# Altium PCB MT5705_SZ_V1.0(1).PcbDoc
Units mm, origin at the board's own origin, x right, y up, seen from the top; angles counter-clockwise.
Board outline 17 x 17 mm, 2 copper layers (Top Layer, Bottom Layer), stack 0.325 mm thick; 41 components, 24 nets, 105 pads, 55 vias.
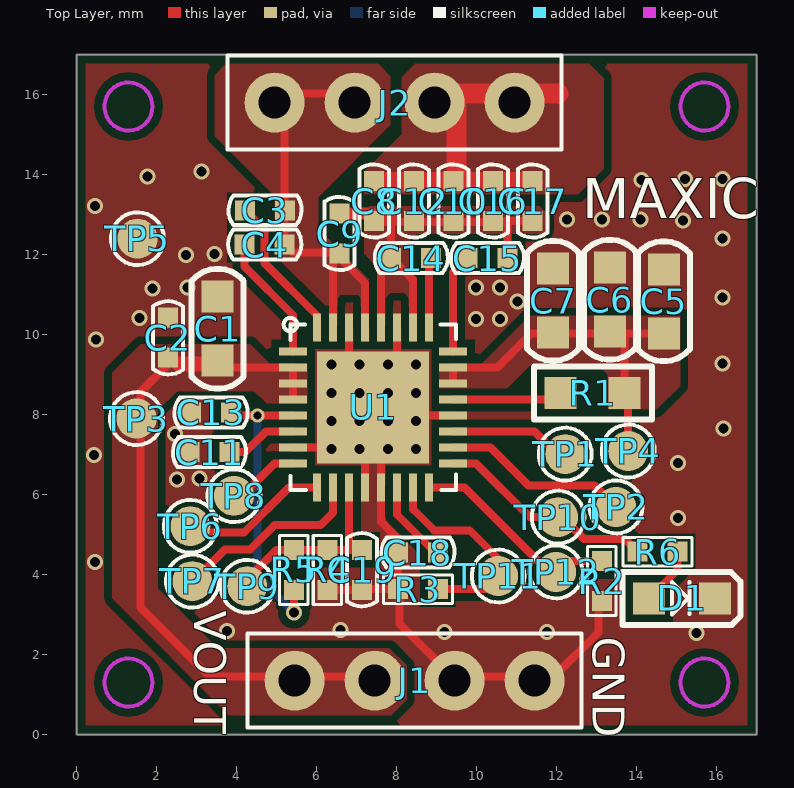
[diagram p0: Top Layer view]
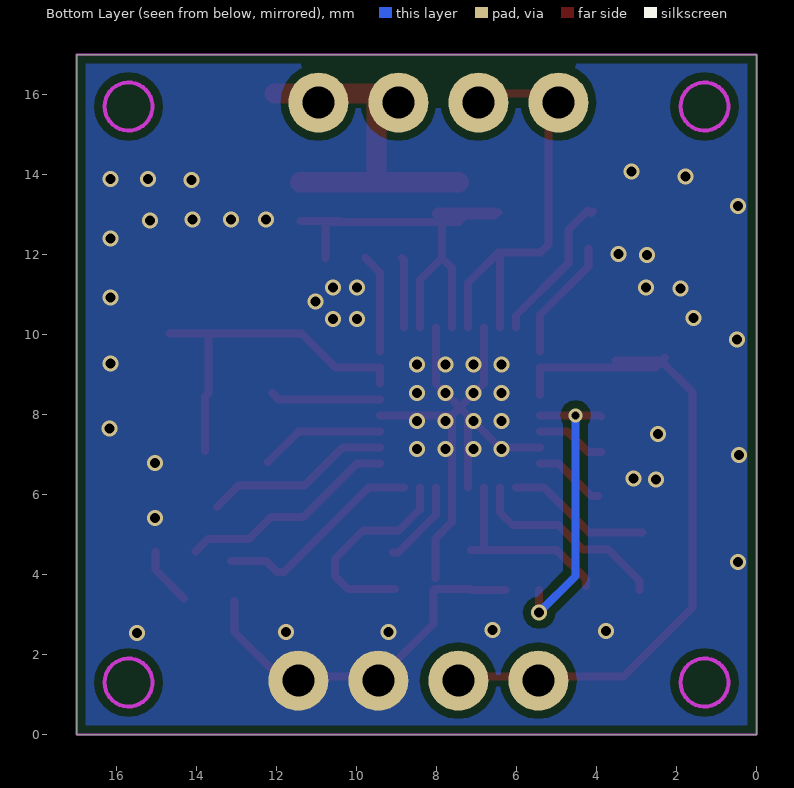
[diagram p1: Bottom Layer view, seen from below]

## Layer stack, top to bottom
Top Solder: solder mask 0.0102, Solder Resist, Dk 3.5
Top Layer: signal copper 0.0356
Dielectric 1: core 0.254, FR-4, Dk 4.2
Bottom Layer: signal copper 0.0356
Bottom Solder: solder mask 0.0102, Solder Resist, Dk 3.5

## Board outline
0,0 17,0 17,17 0,17

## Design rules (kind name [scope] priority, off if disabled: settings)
Clearance Clearance_0.1 [All] p1: gap=0.1
Clearance Clearance_0.2 [All] p2 off: gap=0.2
Clearance Clearance_0.3 [All] p3 off: gap=0.3
ComponentClearance [All] p1 off: gap=0 collisioncheckmode=3 verticalgap=0 showdistances=FALSE
DiffPairsRouting [All] p1: maxlimit=2 minlimit=0.2 mostfreqgap=0.3 toplayer_minwidth=0.2 toplayer_maxwidth=2 toplayer_prefwidth=0.3 bottomlayer_minwidth=0.2 bottomlayer_maxwidth=2 bottomlayer_prefwidth=0.3 maxuncoupledlength=12.7
HoleSize [All] p1: absolutevalues=TRUE maxlimit=5 minlimit=0.025 maxpercent=80.000 minpercent=20.000
HoleToHoleClearance [All] p1: gap=0.2 allowstackedmicrovias=TRUE
MinimumSolderMaskSliver [All] p1: minsoldermaskwidth=0
PlaneConnect [All] p1: planeconnectstyle=Direct reliefexpansion=0.508 reliefentries=4 reliefconductorwidth=0.254 reliefairgap=0.254
PolygonConnect [All] p1: connectstyle=Direct reliefconductorwidth=0.254 reliefentries=4 polygonreliefangle="90 Angle" airgapwidth=0.254
RoutingCorners [All] p1 off: cornerstyle=45-Degree minsetback=2.54 maxsetback=2.54
RoutingVias [All] p1: holewidth=0.4 width=0.7 viastyle="Through Hole" minholewidth=0.25 minwidth=0.4 maxholewidth=1.6 maxwidth=2
SilkToSilkClearance [All] p1: silktosilkclearance=0
SilkToSolderMaskClearance [IsPad] p1: minsilkscreentomaskgap=0 clearancetoexposedcopper=TRUE
SolderMaskExpansion [All] p1: expansion=0.102
Width [All] p1: maxlimit=2 minlimit=0.2 preferedwidth=0.3 minimp=50.000000 maximp=50.000000 favimp=50.000000
20 further rules are at their usual default settings.

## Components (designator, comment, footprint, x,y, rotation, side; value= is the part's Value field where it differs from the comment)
C1 "10uF" 0603C 3.531,10.145 r90 top
C2 "100nF" 0402C 2.286,9.921 r270 top
C3 "15nF" 0402C 4.709,13.106 r0 top
C4 "32nF" 0402C 4.702,12.25 r0 top
C5 "10uF" 0603C 14.681,10.831 r90 top
C6 "10uF" 0603C 13.335,10.871 r90 top
C7 "10uF" 0603C 11.913,10.846 r90 top
C8 "100nF" 0402C 7.442,13.335 r90 top
C9 "3.3nF" 0402C 6.579,12.522 r90 top
C10 "100nF" 0402C 9.423,13.335 r90 top
C11 "1uF" 0402C 3.327,7.061 r180 top
C12 "100nF" 0402C 8.433,13.335 r90 top
C13 "1uF" 0402C 3.368,8.052 r180 top
C14 "15nF" 0402C 8.367,11.913 r0 top
C15 "32nF" 0402C 10.277,11.913 r180 top
C16 "100nF" 0402C 10.414,13.335 r90 top
C17 "NC" 0402C 11.405,13.335 r90 top
C18 "100nF" 0402C 8.534,4.547 r0 top
C19 "100nF" 0402C 7.137,4.115 r90 top
D1 "GREEN" D0603 15.138,3.404 r0 top
J1 "4 HEADER" SIP4-2.00mm 11.455,1.346 r180 top
J2 "COIL" SIP4-2.00mm 4.953,15.799 r0 top
R1 "NC" 0603R 12.903,8.534 r0 top
R2 "100K" 0402R 13.132,3.835 r90 top
R3 "100K" 0402R 8.534,3.632 r0 top
R4 "100K" 0402R 6.274,4.115 r90 top
R5 "NC" 0402R 5.436,4.115 r270 top
R6 "2K" 0402R 14.529,4.572 r180 top
TP1 "" TEST-PAD-S 12.217,7.01 r90 top
TP2 "" TEST-PAD-S 13.487,5.69 r90 top
TP3 "" TEST-PAD-S 1.499,7.899 r90 top
TP4 "" TEST-PAD-S 13.792,7.087 r90 top
TP5 "" TEST-PAD-S 1.524,12.395 r90 top
TP6 "" TEST-PAD-S 2.845,5.207 r90 top
TP7 "" TEST-PAD-S 2.896,3.835 r90 top
TP8 "" TEST-PAD-S 3.937,5.969 r90 top
TP9 "" TEST-PAD-S 4.267,3.708 r90 top
TP10 "" TEST-PAD-S 12.04,5.436 r90 top
TP11 "" TEST-PAD-S 10.541,3.962 r90 top
TP12 "" TEST-PAD-S 11.989,4.064 r90 top
U1 "MT5705" QFN32-EPAD 7.417,8.179 r0 top

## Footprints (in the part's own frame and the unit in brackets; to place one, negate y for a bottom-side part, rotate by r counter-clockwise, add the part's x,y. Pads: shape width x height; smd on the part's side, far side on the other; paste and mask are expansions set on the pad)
0402C [mm]
  rect 0.5x0.5 smd: 1(-0.5,0) 2(0.5,0)
  silkscreen extent -0.91,-0.37 0.92,0.37, body extent -0.5,-0.25 0.5,0.25, height 0.5
0402R [mm]
  rect 0.5x0.5 smd: 1(-0.5,0) 2(0.5,0)
  silkscreen extent -0.86,-0.36 0.86,0.36, body extent -0.5,-0.25 0.5,0.25, height 0.35
0603C [mm]
  rect 0.8x0.8 smd: 1(-0.8,0) 2(0.8,0)
  silkscreen extent -1.5,-0.65 1.5,0.65, body extent -0.8,-0.41 0.8,0.4, height 0.8
0603R [mm]
  rect 0.8x0.8 smd: 1(-0.8,0) 2(0.8,0)
  silkscreen extent -1.46,-0.66 1.49,0.66, body extent -0.8,-0.4 0.8,0.41, height 0.45
D0603 [mm]
  rect 0.8x0.8 smd mask+0.01: A(-0.826,0) K(0.826,0)
  silkscreen extent -1.49,-0.66 1.46,0.66, body extent -0.8,-0.4 0.8,0.4, height 0.6
QFN32-EPAD [mm]
  rect 0.7x0.2 smd mask+0.01: 1(-2,1.4) 2(-2,1) 3(-2,0.6) 4(-2,0.2) 5(-2,-0.2) 6(-2,-0.6) 7(-2,-1) 8(-2,-1.4) 17(2,-1.4) 18(2,-1) 19(2,-0.6) 20(2,-0.2) 21(2,0.2) 22(2,0.6) 23(2,1) 24(2,1.4)
  rect 0.2x0.7 smd mask+0.01: 9(-1.4,-2) 10(-1,-2) 11(-0.6,-2) 12(-0.2,-2) 13(0.2,-2) 14(0.6,-2) 15(1,-2) 16(1.4,-2) 25(1.4,2) 26(1,2) 27(0.6,2) 28(0.2,2) 29(-0.2,2) 30(-0.6,2) 31(-1,2) 32(-1.4,2)
  rect 2.8x2.8 smd mask+0.01: 33(0,0)
  silkscreen extent -2.24,-2.07 2.07,2.24
SIP4-2.00mm [mm]
  round 1.5 hole 0.8: 1(0,0) 2(2,0) 3(4,0) 4(6,0)
  silkscreen extent -1.17,-1.17 7.17,1.17, body extent -1,-1 7,1, height 6
TEST-PAD-S [mm]
  round 1 smd: 1(0,0)
  silkscreen extent -0.66,-0.66 0.66,0.66

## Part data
C1 C2 C3 C4 C5 C6 C7 C8 C9 C10 C11 C12 C13 C14 C15 C16 C17 C18 C19: library part CAP, "Capacitor"
D1: library part LED-GREEN
J1: "4 Pin Header"
J2: library part "4 HEADER", "4 Pin Header"
R1 R2 R3 R4 R5 R6: library part RES
TP1 TP2 TP3 TP4 TP5 TP6 TP7 TP8 TP9 TP10 TP11 TP12: library part TEST-PAD
U1: library part MT5705_QFN32

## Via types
v1: diameter 0.4, hole 0.25, Top Layer to Bottom Layer, 54 vias
v2: diameter 0.35, hole 0.2, Top Layer to Bottom Layer, 1 vias

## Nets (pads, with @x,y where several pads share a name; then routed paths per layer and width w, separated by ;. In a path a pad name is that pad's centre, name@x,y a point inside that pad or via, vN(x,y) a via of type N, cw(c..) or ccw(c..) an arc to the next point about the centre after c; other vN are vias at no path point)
ACN: C8.1 C9.2 C10.1 C12.1 C14.1 C15.1 C16.1 C17.1 U1.26 U1.28 | length 11.8
  Top Layer w0.2: C9.2@6.452,13.048 C9.2@6.579,13.048 ; C8.1@7.23,13.022 7.442,12.81 7.874,12.81 ; U1.28 7.617,11.662 C14.1 ; U1.26 8.417,11.363 C14.1 ; C16.1 C17.1 ; C15.1 10.777,12.766 10.82,12.81 7.874,12.81 ; C14.1 7.867,12.803 7.874,12.81
  Top Layer w0.3: C9.2 7.23,13.022 7.968,13.022
ACP: C3.2 C4.2 C9.1 J2.1 J2.2 U1.29 U1.31 | length 11.9
  Top Layer w0.2: J2.1@4.42,16.027 J2.1@5.461,16.027 ; U1.31 C9.1@6.417,12.048 ; J2.2@6.96,16.027 J2.1@5.461,16.027 ; U1.29 7.217,11.282 6.452,12.048 C9.1@6.417,12.048 ; J2.1@5.461,16.027 5.54,15.949 5.202,15.612 C4.2 5.405,12.048 C9.1@6.417,12.048
GND: C1.2 C2.1 C5.2 C6.2 C7.2 C11.2 C13.2 C18.1 C19.1 D1.K J1.1 J1.2 R2.1 R3.1 R4.1 TP5.1 U1.7 U1.12 U1.13 U1.20 U1.27 U1.30 U1.33 | length 24.4
  Top Layer w0.2: U1.7 6.417,7.179 U1.33@7.217,7.979 ; U1.30 6.817,8.779 U1.33 ; C19.1@7.163,3.615 7.18,3.632 R3.1 ; U1.12 U1.33@7.217,7.979 ; U1.27 8.017,8.779 U1.33 ; 8.026,3.91 8.026,4.902 7.617,5.312 U1.13 U1.33@7.617,7.979 ; R3.1@8.077,3.615 8.077,2.769 9.398,1.448 11.938,1.448 13.056,2.565 R2.1@13.056,3.335 ; U1.20 U1.33@7.617,7.979 ; U1.33@7.217,7.979 U1.33 ; U1.33 U1.33@7.617,7.979
  Top Layer w0.203: R4.1 C19.1 C19.1@7.163,3.615
  other v1: 15.494,2.54 9.195,2.565 11.76,2.565 3.759,2.591 6.604,2.616 0.457,4.318 15.037,5.41 2.515,6.375 3.073,6.401 15.037,6.782 0.432,6.985 6.375,7.137 7.078,7.137 7.781,7.137 8.484,7.137 2.464,7.518 16.18,7.645 6.375,7.84 7.078,7.84 7.781,7.84 8.484,7.84 6.375,8.543 7.078,8.543 7.781,8.543 8.484,8.543 6.375,9.246 7.078,9.246 7.781,9.246 8.484,9.246 16.154,9.271 0.483,9.881 9.982,10.389 10.592,10.389 1.575,10.414 11.024,10.82 16.154,10.922 1.905,11.151 2.769,11.176 9.982,11.176 10.592,11.176 2.743,11.989 3.454,12.014 16.154,12.395 15.164,12.852 12.268,12.878 13.132,12.878 14.097,12.878 0.457,13.208 14.122,13.868 15.215,13.894 16.154,13.894 1.778,13.945 3.124,14.072
GPIO0: TP8.1 U1.8 | length 1.8
  Top Layer w0.2: TP8.1@3.962,5.969 4.14,5.969 4.95,6.779 U1.8
GPIO1: C19.2 R4.2 R5.1 TP9.1 U1.11 | length 4.9
  Top Layer w0.2: 6.817,4.648 U1.11
  Top Layer w0.203: TP9.1 4.267,3.886 4.996,4.615 C19.2
GPIO2: TP6.1 U1.9 | length 3.6
  Top Layer w0.2: TP6.1@2.845,5.055 4.191,5.055 5.315,6.179 U1.9
GPIO3: TP7.1 U1.10 | length 5.1
  Top Layer w0.2: TP7.1@2.921,3.607 2.921,3.835 3.708,4.623 4.343,4.623 4.953,5.232 6.096,5.232 6.417,5.553 U1.10
GPIO5: R6.2 TP10.1 U1.17 | length 5.5
  Top Layer w0.2: U1.17 9.985,6.779 11.328,5.436 TP10.1 12.141,5.436 12.687,4.89 13.711,4.89 R6.2
GPIO6: R3.2 TP11.1 U1.15 | length 5.3
  Top Layer w0.2: U1.15 8.417,5.629 8.941,5.105 9.83,5.105 10.541,4.394 TP11.1 10.211,3.632 R3.2
GPIO7: R2.2 TP12.1 U1.16 | length 5.3
  Top Layer w0.2: U1.16 9.696,6.179 11.811,4.064 TP12.1 12.26,4.335 R2.2
NetC3_1: C3.1 U1.32 | length 3.7
  Top Layer w0.2: C3.1@4.082,13.081 C3.1@4.133,13.03 ; C3.1 4.699,12.617 4.699,11.786 6.017,10.468 U1.32
NetC4_1: C4.1 U1.1 | length 3.1
  Top Layer w0.2: C4.1@4.202,12.148 4.202,11.698 5.417,10.484 U1.1
NetC14_2: C14.2 U1.25 | length 1.8
  Top Layer w0.2: U1.25 8.817,11.862 C14.2
NetC15_2: C15.2 U1.24 | length 2.5
  Top Layer w0.2: U1.24 9.417,11.553 C15.2
NetC18_2: C18.2 U1.14 | length 2.2
  Top Layer w0.2: U1.14 8.017,5.496 8.966,4.547 C18.2@9.093,4.547
NetD1_A: D1.A R6.1 | length 1.5
  Top Layer w0.2: D1.A 15.029,4.119 R6.1
PGATE: TP2.1 U1.18 | length 4.7
  Top Layer w0.2: U1.18 10.347,7.179 11.303,6.223 12.954,6.223 TP2.1
SINK: R1.1 U1.21 | length 2.8
  Top Layer w0.2: U1.21 11.948,8.379 R1.1
USB_IN: TP1.1 U1.19 | length 3.1
  Top Layer w0.2: U1.19 11.446,7.579 TP1.1@12.217,6.807
VCOIL: C8.2 C10.2 C12.2 C16.2 C17.2 J2.3 J2.4 | length 8.8
  Top Layer w0.508: C8.2@7.442,13.81 8.287,13.81 9.131,13.81 C10.2@9.55,13.81 ; C17.2@11.405,13.81 9.976,13.81 C10.2@9.55,13.81 ; 12.05,16.028 9.5,16.028 9.5,13.86 C10.2@9.55,13.81
VDD18V: C11.1 U1.6 | length 1.8
  Top Layer w0.2: C11.1@3.878,7.061 4.216,7.061 4.734,7.579 U1.6
VDD50V: C13.1 R5.2 U1.5 | length 7.4
  Top Layer w0.2: C13.1@3.893,7.95 3.922,7.979 U1.5 ; v1(5.436,3.048) R5.2
  Bottom Layer w0.2: v2(4.521,7.976) 4.521,3.962 v1(5.436,3.048)
VOUT: C1.1 C2.2 J1.3 J1.4 TP3.1 U1.2 U1.3 U1.4 | length 17.5
  Top Layer w0.2: C2.2 C2.2@2.374,9.333 ; C1.1 2.385,9.345 C2.2@2.374,9.333 ; 5.417,8.484 U1.3 U1.2 2.528,9.179 C2.2@2.374,9.333 ; J1.3@6.858,1.448 3.327,1.448 1.6,3.175 1.6,8.56 C2.2@2.374,9.333
VRECT: C5.1 C6.1 C7.1 R1.2 TP4.1 U1.22 U1.23 | length 9
  Top Layer w0.2: U1.22 U1.23 10.525,9.179 11.377,10.031 C6.1@13.64,10.031 ; TP4.1 13.792,8.445 R1.2 13.703,9.967 C6.1@13.64,10.031 ; C5.1 C6.1@13.64,10.031

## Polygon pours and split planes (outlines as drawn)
VRECT on Top Layer "Top Overlay-No Net" (solid, remove dead copper, pour order 13): 9.068,8.661 10.77,8.661 11.379,9.271 13.005,9.271 13.284,8.992 13.284,8.153 13.31,8.128 14.503,8.128 15.088,8.712 15.088,10.465 11.328,10.465 10.135,9.271 9.068,9.271
ACN on Top Layer "Top Overlay-No Net" (solid, remove dead copper, pour order 11): 8.306,9.83 8.306,10.922 8.179,11.049 7.849,11.049 7.722,10.922 7.722,9.83 7.518,9.83 7.518,11.684 7.188,12.014 7.188,13.081 7.315,13.208 11.582,13.208 11.735,13.056 11.735,12.598 11.659,12.522 8.509,12.522 8.331,12.344 8.331,11.608 8.509,11.43 8.509,9.83
VOUT on Top Layer "Top Overlay-No Net" (solid, remove dead copper, pour order 12): 5.766,8.28 4.75,8.28 4.445,8.585 2.515,8.585 2.032,8.103 2.032,3.658 3.531,2.159 7.823,2.159 8.255,1.727 8.255,0.864 7.874,0.483 3.81,0.483 0.889,3.404 0.889,9.042 1.6,9.754 4.343,9.754 4.826,9.271 5.766,9.271
ACP on Top Layer "Top Overlay-No Net" (solid, remove dead copper, pour order 10): 6.325,10.617 4.953,11.989 4.953,13.462 3.454,14.961 3.454,16.485 3.734,16.764 7.544,16.764 7.849,16.459 7.849,15.24 6.045,13.437 6.045,12.649 7.315,11.379 7.315,9.83 7.112,9.83 7.112,10.922 7.036,10.998 6.604,10.998 6.528,10.922 6.528,9.83 6.325,9.83
VCOIL on Top Layer "Top Overlay-No Net" (solid, remove dead copper, pour order 9): 7.188,13.513 12.548,13.513 13.183,14.148 13.183,16.408 12.776,16.815 8.509,16.815 8.128,16.434 8.128,15.011 7.188,14.072
GND on Top Layer "Top Overlay-No Net" (solid, remove dead copper, pour order 15): 0,16.993 0,0 17,0 17,16.993
GND on Bottom Layer "Top Overlay-No Net" (solid, remove dead copper, pour order 14): 0,16.993 0,0 17,0 17,16.993

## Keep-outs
Keep-Out Layer:
  circle w0.1: c1.3,1.3 r0.6
  circle w0.1: c1.3,15.7 r0.6
  circle w0.1: c15.7,15.7 r0.6
  circle w0.1: c15.7,1.3 r0.6
  lines w0.051: 0,0 17,0 17,17 0,17 0,0

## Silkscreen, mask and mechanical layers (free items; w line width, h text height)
Top Overlay:
  text "MAXIC" at 12.649,12.903 h1
  text "VOUT" at 2.946,3.099 h0.8 r270
  text "GND" at 12.903,2.438 h0.8 r270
